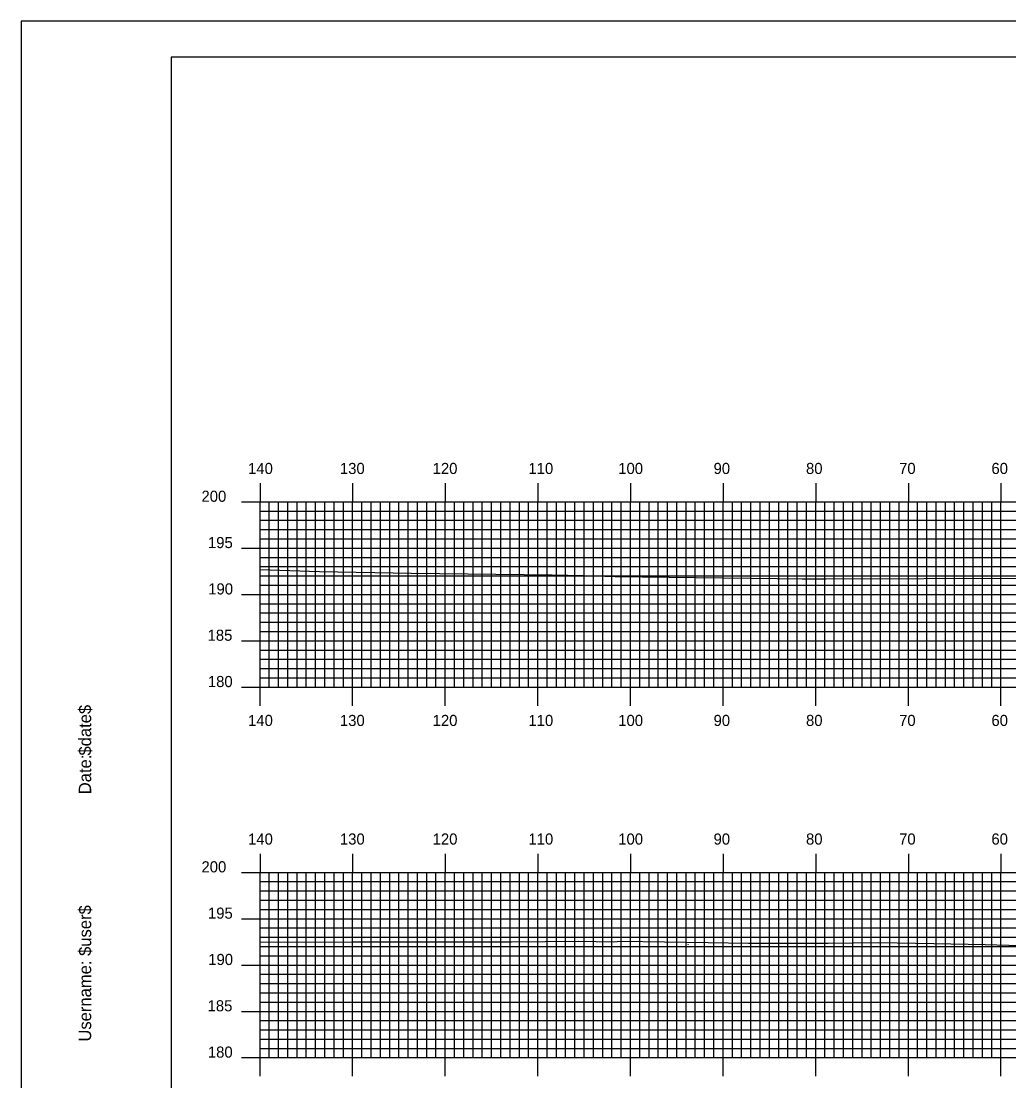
# Model space of a CAD drawing. Extents: x 1798388 to 1798731, y 442591 to 442811.
# Drawn here: x 1798387.7 to 1798494.3, y 442696.2 to 442810.5 of the extents above; entities that cross this region are included whole.
import ezdxf

# ---------------------------------------------------------------- set-up
doc = ezdxf.new("R2010")
doc.units = 0
for name, color, linetype in [('BORDER', 7, 'Continuous'), ('H_V ANNOTATION', 7, 'Continuous'), ('M_Utilities_Pole', 7, 'Continuous'), ('MAJOR', 7, 'Continuous'), ('MINOR', 7, 'Continuous'), ('PLOT BOUNDARY', 7, 'Continuous'), ('S_Roadway_Centerline', 7, 'Continuous')]:
    doc.layers.add(name, color=color, linetype=linetype)

msp = doc.modelspace()

# ---------------------------------------------------------------- linework, layer by layer
at = {"layer": 'BORDER'}
msp.add_lwpolyline([(1798403.87, 442596.67), (1798723.87, 442596.67), (1798723.87, 442806.67), (1798403.87, 442806.67)], close=True, dxfattribs=at)
at = {"layer": 'M_Utilities_Pole'}
msp.add_line((1798459.7, 442710.88), (1798459.7, 442710.86), dxfattribs=at)
msp.add_circle((1798459.7, 442710.87), 0.00417, dxfattribs=at)
at = {"layer": 'MAJOR'}
for p, q in [((1798413.47, 442760.67), (1798413.47, 442758.67)), ((1798423.47, 442760.67), (1798423.47, 442758.67)), ((1798433.47, 442760.67), (1798433.47, 442758.67)), ((1798443.47, 442760.67), (1798443.47, 442758.67)), ((1798453.47, 442760.67), (1798453.47, 442758.67)), ((1798463.47, 442760.67), (1798463.47, 442758.67)), ((1798473.47, 442760.67), (1798473.47, 442758.67)), ((1798483.47, 442760.67), (1798483.47, 442758.67)), ((1798493.47, 442760.67), (1798493.47, 442758.67)), ((1798411.47, 442758.67), (1798413.47, 442758.67)), ((1798413.47, 442758.67), (1798693.47, 442758.67)), ((1798413.47, 442738.67), (1798413.47, 442758.67)), ((1798413.47, 442738.67), (1798413.47, 442758.67)), ((1798413.47, 442758.67), (1798693.47, 442758.67)), ((1798423.47, 442738.67), (1798423.47, 442758.67)), ((1798433.47, 442738.67), (1798433.47, 442758.67)), ((1798443.47, 442738.67), (1798443.47, 442758.67)), ((1798453.47, 442738.67), (1798453.47, 442758.67)), ((1798463.47, 442738.67), (1798463.47, 442758.67)), ((1798473.47, 442738.67), (1798473.47, 442758.67)), ((1798483.47, 442738.67), (1798483.47, 442758.67)), ((1798493.47, 442738.67), (1798493.47, 442758.67)), ((1798411.47, 442753.67), (1798413.47, 442753.67)), ((1798413.47, 442753.67), (1798693.47, 442753.67)), ((1798411.47, 442748.67), (1798413.47, 442748.67)), ((1798413.47, 442748.67), (1798693.47, 442748.67)), ((1798411.47, 442743.67), (1798413.47, 442743.67)), ((1798413.47, 442743.67), (1798693.47, 442743.67)), ((1798411.47, 442738.67), (1798413.47, 442738.67)), ((1798413.47, 442738.67), (1798693.47, 442738.67)), ((1798413.47, 442738.67), (1798693.47, 442738.67)), ((1798413.47, 442736.66), (1798413.47, 442738.67)), ((1798423.47, 442736.66), (1798423.47, 442738.67)), ((1798433.47, 442736.66), (1798433.47, 442738.67)), ((1798443.47, 442736.66), (1798443.47, 442738.67)), ((1798453.47, 442736.66), (1798453.47, 442738.67)), ((1798463.47, 442736.66), (1798463.47, 442738.67)), ((1798473.47, 442736.66), (1798473.47, 442738.67)), ((1798483.47, 442736.66), (1798483.47, 442738.67)), ((1798493.47, 442736.66), (1798493.47, 442738.67)), ((1798413.47, 442720.67), (1798413.47, 442718.67)), ((1798423.47, 442720.67), (1798423.47, 442718.67)), ((1798433.47, 442720.67), (1798433.47, 442718.67)), ((1798443.47, 442720.67), (1798443.47, 442718.67)), ((1798453.47, 442720.67), (1798453.47, 442718.67)), ((1798463.47, 442720.67), (1798463.47, 442718.67)), ((1798473.47, 442720.67), (1798473.47, 442718.67)), ((1798483.47, 442720.67), (1798483.47, 442718.67)), ((1798493.47, 442720.67), (1798493.47, 442718.67)), ((1798411.47, 442718.67), (1798413.47, 442718.67)), ((1798413.47, 442718.67), (1798693.47, 442718.67)), ((1798413.47, 442698.67), (1798413.47, 442718.67)), ((1798413.47, 442698.67), (1798413.47, 442718.67)), ((1798413.47, 442718.67), (1798693.47, 442718.67)), ((1798423.47, 442698.67), (1798423.47, 442718.67)), ((1798433.47, 442698.67), (1798433.47, 442718.67)), ((1798443.47, 442698.67), (1798443.47, 442718.67)), ((1798453.47, 442698.67), (1798453.47, 442718.67)), ((1798463.47, 442698.67), (1798463.47, 442718.67)), ((1798473.47, 442698.67), (1798473.47, 442718.67)), ((1798483.47, 442698.67), (1798483.47, 442718.67)), ((1798493.47, 442698.67), (1798493.47, 442718.67)), ((1798411.47, 442713.67), (1798413.47, 442713.67)), ((1798413.47, 442713.67), (1798693.47, 442713.67)), ((1798411.47, 442708.67), (1798413.47, 442708.67)), ((1798413.47, 442708.67), (1798693.47, 442708.67)), ((1798411.47, 442703.67), (1798413.47, 442703.67)), ((1798413.47, 442703.67), (1798693.47, 442703.67)), ((1798411.47, 442698.67), (1798413.47, 442698.67)), ((1798413.47, 442698.67), (1798693.47, 442698.67)), ((1798413.47, 442698.67), (1798693.47, 442698.67)), ((1798413.47, 442696.66), (1798413.47, 442698.67)), ((1798423.47, 442696.66), (1798423.47, 442698.67)), ((1798433.47, 442696.66), (1798433.47, 442698.67)), ((1798443.47, 442696.66), (1798443.47, 442698.67)), ((1798453.47, 442696.66), (1798453.47, 442698.67)), ((1798463.47, 442696.66), (1798463.47, 442698.67)), ((1798473.47, 442696.66), (1798473.47, 442698.67)), ((1798483.47, 442696.66), (1798483.47, 442698.67)), ((1798493.47, 442696.66), (1798493.47, 442698.67))]:
    msp.add_line(p, q, dxfattribs=at)
at = {"layer": 'MINOR'}
for p, q in [((1798414.47, 442738.67), (1798414.47, 442758.67)), ((1798415.47, 442738.67), (1798415.47, 442758.67)), ((1798416.47, 442738.67), (1798416.47, 442758.67)), ((1798417.47, 442738.67), (1798417.47, 442758.67)), ((1798418.47, 442738.67), (1798418.47, 442758.67)), ((1798419.47, 442738.67), (1798419.47, 442758.67)), ((1798420.47, 442738.67), (1798420.47, 442758.67)), ((1798421.47, 442738.67), (1798421.47, 442758.67)), ((1798422.47, 442738.67), (1798422.47, 442758.67)), ((1798424.47, 442738.67), (1798424.47, 442758.67)), ((1798425.47, 442738.67), (1798425.47, 442758.67)), ((1798426.47, 442738.67), (1798426.47, 442758.67)), ((1798427.47, 442738.67), (1798427.47, 442758.67)), ((1798428.47, 442738.67), (1798428.47, 442758.67)), ((1798429.47, 442738.67), (1798429.47, 442758.67)), ((1798430.47, 442738.67), (1798430.47, 442758.67)), ((1798431.47, 442738.67), (1798431.47, 442758.67)), ((1798432.47, 442738.67), (1798432.47, 442758.67)), ((1798434.47, 442738.67), (1798434.47, 442758.67)), ((1798435.47, 442738.67), (1798435.47, 442758.67)), ((1798436.47, 442738.67), (1798436.47, 442758.67)), ((1798437.47, 442738.67), (1798437.47, 442758.67)), ((1798438.47, 442738.67), (1798438.47, 442758.67)), ((1798439.47, 442738.67), (1798439.47, 442758.67)), ((1798440.47, 442738.67), (1798440.47, 442758.67)), ((1798441.47, 442738.67), (1798441.47, 442758.67)), ((1798442.47, 442738.67), (1798442.47, 442758.67)), ((1798444.47, 442738.67), (1798444.47, 442758.67)), ((1798445.47, 442738.67), (1798445.47, 442758.67)), ((1798446.47, 442738.67), (1798446.47, 442758.67)), ((1798447.47, 442738.67), (1798447.47, 442758.67)), ((1798448.47, 442738.67), (1798448.47, 442758.67)), ((1798449.47, 442738.67), (1798449.47, 442758.67)), ((1798450.47, 442738.67), (1798450.47, 442758.67)), ((1798451.47, 442738.67), (1798451.47, 442758.67)), ((1798452.47, 442738.67), (1798452.47, 442758.67)), ((1798454.47, 442738.67), (1798454.47, 442758.67)), ((1798455.47, 442738.67), (1798455.47, 442758.67)), ((1798456.47, 442738.67), (1798456.47, 442758.67)), ((1798457.47, 442738.67), (1798457.47, 442758.67)), ((1798458.47, 442738.67), (1798458.47, 442758.67)), ((1798459.47, 442738.67), (1798459.47, 442758.67)), ((1798460.47, 442738.67), (1798460.47, 442758.67)), ((1798461.47, 442738.67), (1798461.47, 442758.67)), ((1798462.47, 442738.67), (1798462.47, 442758.67)), ((1798464.47, 442738.67), (1798464.47, 442758.67)), ((1798465.47, 442738.67), (1798465.47, 442758.67)), ((1798466.47, 442738.67), (1798466.47, 442758.67)), ((1798467.47, 442738.67), (1798467.47, 442758.67)), ((1798468.47, 442738.67), (1798468.47, 442758.67)), ((1798469.47, 442738.67), (1798469.47, 442758.67)), ((1798470.47, 442738.67), (1798470.47, 442758.67)), ((1798471.47, 442738.67), (1798471.47, 442758.67)), ((1798472.47, 442738.67), (1798472.47, 442758.67)), ((1798474.47, 442738.67), (1798474.47, 442758.67)), ((1798475.47, 442738.67), (1798475.47, 442758.67)), ((1798476.47, 442738.67), (1798476.47, 442758.67)), ((1798477.47, 442738.67), (1798477.47, 442758.67)), ((1798478.47, 442738.67), (1798478.47, 442758.67)), ((1798479.47, 442738.67), (1798479.47, 442758.67)), ((1798480.47, 442738.67), (1798480.47, 442758.67)), ((1798481.47, 442738.67), (1798481.47, 442758.67)), ((1798482.47, 442738.67), (1798482.47, 442758.67)), ((1798484.47, 442738.67), (1798484.47, 442758.67)), ((1798485.47, 442738.67), (1798485.47, 442758.67)), ((1798486.47, 442738.67), (1798486.47, 442758.67)), ((1798487.47, 442738.67), (1798487.47, 442758.67)), ((1798488.47, 442738.67), (1798488.47, 442758.67)), ((1798489.47, 442738.67), (1798489.47, 442758.67)), ((1798490.47, 442738.67), (1798490.47, 442758.67)), ((1798491.47, 442738.67), (1798491.47, 442758.67)), ((1798492.47, 442738.67), (1798492.47, 442758.67)), ((1798413.47, 442757.67), (1798693.47, 442757.67)), ((1798413.47, 442757.67), (1798415.47, 442757.67)), ((1798413.47, 442756.67), (1798693.47, 442756.67)), ((1798413.47, 442756.67), (1798415.47, 442756.67)), ((1798413.47, 442755.67), (1798693.47, 442755.67)), ((1798413.47, 442755.67), (1798415.47, 442755.67)), ((1798413.47, 442754.67), (1798693.47, 442754.67)), ((1798413.47, 442754.67), (1798415.47, 442754.67)), ((1798413.47, 442752.67), (1798693.47, 442752.67)), ((1798413.47, 442752.67), (1798415.47, 442752.67)), ((1798413.47, 442751.67), (1798693.47, 442751.67)), ((1798413.47, 442751.67), (1798415.47, 442751.67)), ((1798413.47, 442750.67), (1798693.47, 442750.67)), ((1798413.47, 442750.67), (1798415.47, 442750.67)), ((1798413.47, 442749.67), (1798693.47, 442749.67)), ((1798413.47, 442749.67), (1798415.47, 442749.67)), ((1798413.47, 442747.67), (1798693.47, 442747.67)), ((1798413.47, 442747.67), (1798415.47, 442747.67)), ((1798413.47, 442746.67), (1798693.47, 442746.67)), ((1798413.47, 442746.67), (1798415.47, 442746.67)), ((1798413.47, 442745.67), (1798693.47, 442745.67)), ((1798413.47, 442745.67), (1798415.47, 442745.67)), ((1798413.47, 442744.67), (1798693.47, 442744.67)), ((1798413.47, 442744.67), (1798415.47, 442744.67)), ((1798413.47, 442742.67), (1798693.47, 442742.67)), ((1798413.47, 442742.67), (1798415.47, 442742.67)), ((1798413.47, 442741.67), (1798693.47, 442741.67)), ((1798413.47, 442741.67), (1798415.47, 442741.67)), ((1798413.47, 442740.67), (1798693.47, 442740.67)), ((1798413.47, 442740.67), (1798415.47, 442740.67)), ((1798413.47, 442739.67), (1798693.47, 442739.67)), ((1798413.47, 442739.67), (1798415.47, 442739.67)), ((1798414.47, 442698.67), (1798414.47, 442718.67)), ((1798415.47, 442698.67), (1798415.47, 442718.67)), ((1798416.47, 442698.67), (1798416.47, 442718.67)), ((1798417.47, 442698.67), (1798417.47, 442718.67)), ((1798418.47, 442698.67), (1798418.47, 442718.67)), ((1798419.47, 442698.67), (1798419.47, 442718.67)), ((1798420.47, 442698.67), (1798420.47, 442718.67)), ((1798421.47, 442698.67), (1798421.47, 442718.67)), ((1798422.47, 442698.67), (1798422.47, 442718.67)), ((1798424.47, 442698.67), (1798424.47, 442718.67)), ((1798425.47, 442698.67), (1798425.47, 442718.67)), ((1798426.47, 442698.67), (1798426.47, 442718.67)), ((1798427.47, 442698.67), (1798427.47, 442718.67)), ((1798428.47, 442698.67), (1798428.47, 442718.67)), ((1798429.47, 442698.67), (1798429.47, 442718.67)), ((1798430.47, 442698.67), (1798430.47, 442718.67)), ((1798431.47, 442698.67), (1798431.47, 442718.67)), ((1798432.47, 442698.67), (1798432.47, 442718.67)), ((1798434.47, 442698.67), (1798434.47, 442718.67)), ((1798435.47, 442698.67), (1798435.47, 442718.67)), ((1798436.47, 442698.67), (1798436.47, 442718.67)), ((1798437.47, 442698.67), (1798437.47, 442718.67)), ((1798438.47, 442698.67), (1798438.47, 442718.67)), ((1798439.47, 442698.67), (1798439.47, 442718.67)), ((1798440.47, 442698.67), (1798440.47, 442718.67)), ((1798441.47, 442698.67), (1798441.47, 442718.67)), ((1798442.47, 442698.67), (1798442.47, 442718.67)), ((1798444.47, 442698.67), (1798444.47, 442718.67)), ((1798445.47, 442698.67), (1798445.47, 442718.67)), ((1798446.47, 442698.67), (1798446.47, 442718.67)), ((1798447.47, 442698.67), (1798447.47, 442718.67)), ((1798448.47, 442698.67), (1798448.47, 442718.67)), ((1798449.47, 442698.67), (1798449.47, 442718.67)), ((1798450.47, 442698.67), (1798450.47, 442718.67)), ((1798451.47, 442698.67), (1798451.47, 442718.67)), ((1798452.47, 442698.67), (1798452.47, 442718.67)), ((1798454.47, 442698.67), (1798454.47, 442718.67)), ((1798455.47, 442698.67), (1798455.47, 442718.67)), ((1798456.47, 442698.67), (1798456.47, 442718.67)), ((1798457.47, 442698.67), (1798457.47, 442718.67)), ((1798458.47, 442698.67), (1798458.47, 442718.67)), ((1798459.47, 442698.67), (1798459.47, 442718.67)), ((1798460.47, 442698.67), (1798460.47, 442718.67)), ((1798461.47, 442698.67), (1798461.47, 442718.67)), ((1798462.47, 442698.67), (1798462.47, 442718.67)), ((1798464.47, 442698.67), (1798464.47, 442718.67)), ((1798465.47, 442698.67), (1798465.47, 442718.67)), ((1798466.47, 442698.67), (1798466.47, 442718.67)), ((1798467.47, 442698.67), (1798467.47, 442718.67)), ((1798468.47, 442698.67), (1798468.47, 442718.67)), ((1798469.47, 442698.67), (1798469.47, 442718.67)), ((1798470.47, 442698.67), (1798470.47, 442718.67)), ((1798471.47, 442698.67), (1798471.47, 442718.67)), ((1798472.47, 442698.67), (1798472.47, 442718.67)), ((1798474.47, 442698.67), (1798474.47, 442718.67)), ((1798475.47, 442698.67), (1798475.47, 442718.67)), ((1798476.47, 442698.67), (1798476.47, 442718.67)), ((1798477.47, 442698.67), (1798477.47, 442718.67)), ((1798478.47, 442698.67), (1798478.47, 442718.67)), ((1798479.47, 442698.67), (1798479.47, 442718.67)), ((1798480.47, 442698.67), (1798480.47, 442718.67)), ((1798481.47, 442698.67), (1798481.47, 442718.67)), ((1798482.47, 442698.67), (1798482.47, 442718.67)), ((1798484.47, 442698.67), (1798484.47, 442718.67)), ((1798485.47, 442698.67), (1798485.47, 442718.67)), ((1798486.47, 442698.67), (1798486.47, 442718.67)), ((1798487.47, 442698.67), (1798487.47, 442718.67)), ((1798488.47, 442698.67), (1798488.47, 442718.67)), ((1798489.47, 442698.67), (1798489.47, 442718.67)), ((1798490.47, 442698.67), (1798490.47, 442718.67)), ((1798491.47, 442698.67), (1798491.47, 442718.67)), ((1798492.47, 442698.67), (1798492.47, 442718.67)), ((1798413.47, 442717.67), (1798693.47, 442717.67)), ((1798413.47, 442717.67), (1798415.47, 442717.67)), ((1798413.47, 442716.67), (1798693.47, 442716.67)), ((1798413.47, 442716.67), (1798415.47, 442716.67)), ((1798413.47, 442715.67), (1798693.47, 442715.67)), ((1798413.47, 442715.67), (1798415.47, 442715.67)), ((1798413.47, 442714.67), (1798693.47, 442714.67)), ((1798413.47, 442714.67), (1798415.47, 442714.67)), ((1798413.47, 442712.67), (1798693.47, 442712.67)), ((1798413.47, 442712.67), (1798415.47, 442712.67)), ((1798413.47, 442711.67), (1798693.47, 442711.67)), ((1798413.47, 442711.67), (1798415.47, 442711.67)), ((1798413.47, 442710.67), (1798693.47, 442710.67)), ((1798413.47, 442710.67), (1798415.47, 442710.67)), ((1798413.47, 442709.67), (1798693.47, 442709.67)), ((1798413.47, 442709.67), (1798415.47, 442709.67)), ((1798413.47, 442707.67), (1798693.47, 442707.67)), ((1798413.47, 442707.67), (1798415.47, 442707.67)), ((1798413.47, 442706.67), (1798693.47, 442706.67)), ((1798413.47, 442706.67), (1798415.47, 442706.67)), ((1798413.47, 442705.67), (1798693.47, 442705.67)), ((1798413.47, 442705.67), (1798415.47, 442705.67)), ((1798413.47, 442704.67), (1798693.47, 442704.67)), ((1798413.47, 442704.67), (1798415.47, 442704.67)), ((1798413.47, 442702.67), (1798693.47, 442702.67)), ((1798413.47, 442702.67), (1798415.47, 442702.67)), ((1798413.47, 442701.67), (1798693.47, 442701.67)), ((1798413.47, 442701.67), (1798415.47, 442701.67)), ((1798413.47, 442700.67), (1798693.47, 442700.67)), ((1798413.47, 442700.67), (1798415.47, 442700.67)), ((1798413.47, 442699.67), (1798693.47, 442699.67)), ((1798413.47, 442699.67), (1798415.47, 442699.67))]:
    msp.add_line(p, q, dxfattribs=at)
at = {"layer": 'PLOT BOUNDARY'}
msp.add_lwpolyline([(1798387.68, 442590.55), (1798727.68, 442590.55), (1798727.68, 442810.55), (1798387.68, 442810.55)], close=True, dxfattribs=at)
at = {"layer": 'S_Roadway_Centerline'}
for points in [[(1798413.47, 442751.35), (1798419.89, 442751.16), (1798429.84, 442750.95), (1798445, 442750.79), (1798448.44, 442750.73), (1798451.83, 442750.62), (1798469.31, 442750.38), (1798472, 442750.34), (1798474.57, 442750.35), (1798495.75, 442750.41)], [(1798413.47, 442711.14), (1798423.49, 442711.16), (1798430.86, 442711.16), (1798432.12, 442711.16), (1798432.63, 442711.17), (1798437.22, 442711.17), (1798440.64, 442711.19), (1798447.89, 442711.25), (1798451.65, 442711.19), (1798452.44, 442711.26), (1798461.86, 442711.1), (1798466.21, 442711.03), (1798474.81, 442711.03), (1798480.28, 442711.09), (1798486.23, 442710.99), (1798491.78, 442710.9), (1798496.88, 442710.74)]]:
    msp.add_lwpolyline(points, dxfattribs=at)

# ---------------------------------------------------------------- texts
at = {"layer": 'BORDER'}
for s, p in [('$date$', (1798395.24, 442731.28)), ('Date:', (1798395.24, 442727.1)), ('$user$', (1798395.24, 442709.65)), ('Username:', (1798395.24, 442700.4))]:
    msp.add_text(s, height=1.339, rotation=90, dxfattribs=at).set_placement(p)
at = {"layer": 'H_V ANNOTATION'}
for s, p in [('140', (1798412.18, 442761.67)), ('130', (1798422.1, 442761.67)), ('120', (1798432.11, 442761.67)), ('110', (1798442.45, 442761.67)), ('100', (1798452.15, 442761.67)), ('90', (1798462.44, 442761.67)), ('80', (1798472.42, 442761.67)), ('70', (1798482.47, 442761.67)), ('60', (1798492.44, 442761.67)), ('200', (1798407.15, 442758.67)), ('195', (1798407.85, 442753.67)), ('190', (1798407.88, 442748.67)), ('185', (1798407.81, 442743.67)), ('180', (1798407.84, 442738.67)), ('140', (1798412.18, 442734.47)), ('130', (1798422.1, 442734.47)), ('120', (1798432.11, 442734.47)), ('110', (1798442.45, 442734.47)), ('100', (1798452.15, 442734.47)), ('90', (1798462.44, 442734.47)), ('80', (1798472.42, 442734.47)), ('70', (1798482.47, 442734.47)), ('60', (1798492.44, 442734.47)), ('140', (1798412.18, 442721.67)), ('130', (1798422.1, 442721.67)), ('120', (1798432.11, 442721.67)), ('110', (1798442.45, 442721.67)), ('100', (1798452.15, 442721.67)), ('90', (1798462.44, 442721.67)), ('80', (1798472.42, 442721.67)), ('70', (1798482.47, 442721.67)), ('60', (1798492.44, 442721.67)), ('200', (1798407.15, 442718.67)), ('195', (1798407.85, 442713.67)), ('190', (1798407.88, 442708.67)), ('185', (1798407.81, 442703.67)), ('180', (1798407.84, 442698.67))]:
    msp.add_text(s, height=1.2, dxfattribs=at).set_placement(p)
at = {"layer": 'MAJOR'}
for p in [(1798413.46, 442738.67), (1798413.46, 442698.67)]:
    msp.add_text('-', height=0.012, dxfattribs=at).set_placement(p)

doc.saveas('drawing.dxf')
